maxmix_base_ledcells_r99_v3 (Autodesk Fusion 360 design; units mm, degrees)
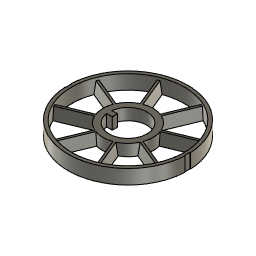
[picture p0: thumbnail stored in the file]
sketch "Sketch1" plane through (0, 0, 0) normal (0, 0, 1) x axis (1, 0, 0)
  circle C1 centre (0, 0) radius 21.7
  circle C2 centre (0, 0) radius 20.5
  circle C3 centre (0, 0) radius 9.125
  circle C4 centre (0, 0) radius 6.9
  point P1 (0, 0)
  point P2 (0, 0)
  coincident P1 P2
  concentric C1 C2
  concentric C2 C3
  concentric C2 C4
  dimension "d1" diameter C1 = 43.4
  dimension "d2" diameter C2 = 41
  dimension "d3" diameter C3 = 18.25
  dimension "d4" diameter C4 = 13.8
extrude "Extrude1" new body sketch "Sketch1" profile of C1 C2 along normal blind 5.2
extrude "Extrude2" new body sketch "Sketch1" profile of C3 C4 along normal blind 4.2
sketch "Sketch3" plane through (0, 0, 0) normal (0, 0, 1) x axis (1, 0, 0)
  line L1 (8.3042, 20.0482) -> (0, 0)
  line L2 (1.6888, 6.6901) -> (7.3715, 20.4096)
  line L3 (9.2193, 19.6442) -> (3.5365, 5.9248)
  line L4 (0, 20) -> (0, 2.5)
  circle C1 centre (0, 0) radius 21.7
  circle C2 centre (0, 0) radius 6.9
  point P4 (7.3715, 20.4096)
  point P7 (9.2193, 19.6442)
  point P3 (8.3042, 20.0482)
  point P5 (1.6888, 6.6901)
  point P6 (3.5365, 5.9248)
  point P1 (0, 0)
  point P2 (0, 0)
  parallel L1 L3
  symmetric L1 L2 L3
  coincident P4 C1
  coincident P7 C1
  coincident P3 C1
  coincident P5 C2
  coincident P6 C2
  coincident P1 P2
  dimension "d16" distance L2 L3 = 2
  dimension "d29" angle L1 L4 = 22.5
sketch "Sketch4" plane through (0, 0, 4.2) normal (0, 0, 1) x axis (-1, 0, 0)
  line L1 (-8.0746, -19.4939) -> (0, 0)
  line L2 (-2.736, -7.6505) -> (-7.7036, -19.6434)
  line L3 (-3.4751, -7.3443) -> (-8.4427, -19.3373)
  line L4 (0, -20) -> (0, -2.5)
  circle C1 centre (0, 0) radius 6.9
  circle C2 centre (0, 0) radius 21.7
  circle C3 centre (0, 0) radius 9.125
  circle C4 centre (0, 0) radius 20.5
  circle C5 centre (0, 0) radius 21.1
  circle C6 centre (0, 0) radius 8.125
  point P1 (0, 0)
  point P3 (0, 0)
  point P6 (-8.4427, -19.3373)
  point P4 (-7.7036, -19.6434)
  point P8 (-8.0746, -19.4939)
  point P13 (0, 0)
  point P7 (-3.4751, -7.3443)
  point P5 (-2.736, -7.6505)
  symmetric L1 L2 L3
  coincident P1 P3
  concentric C3 C5
  coincident P6 C5
  coincident P4 C5
  coincident P8 C5
  coincident P1 P13
  coincident P7 C6
  coincident P5 C6
  dimension "d17" distance L2 L3 = 0.8
  dimension "d20" distance C2 C5 = 0.6
  dimension "d21" distance C3 C6 = 1
  dimension "d30" angle L1 L4 = 22.5
loft "Loft3" sketch "Sketch3" + "Sketch4"
circular_pattern "C-Pattern2" TotalAngle 360
sketch "Sketch2" plane through (0, 0, 0) normal (0, 0, 1) x axis (1, 0, 0)
  line L1 (21.7, 0) -> (-21.7, 0)
  line L2 (0, -6.9) -> (0, 0)
  line L3 (21.5, 1) -> (21.6769, 1)
  line L4 (21.5, -1) -> (21.5, 1)
  line L5 (21.6769, -1) -> (21.5, -1)
  line L6 (-21.5, 1) -> (-21.6769, 1)
  line L7 (-21.5, -1) -> (-21.5, 1)
  line L8 (-21.6769, -1) -> (-21.5, -1)
  line L9 (-4.75, 0.95) -> (-6.8343, 0.95)
  line L10 (-4.75, -0.95) -> (-4.75, 0.95)
  line L11 (-6.8343, -0.95) -> (-4.75, -0.95)
  circle C1 centre (0, 0) radius 6.9
  circle C2 centre (0, 0) radius 21.7
  point P3 (0, 0)
  point P4 (0, 0)
  point P5 (0, -6.9)
  point P1 (0, 0)
  point P6 (21.6769, 1)
  point P9 (21.6769, -1)
  point P10 (-21.6769, 1)
  point P13 (-21.6769, -1)
  point P14 (-21.7, 0)
  point P15 (21.7, 0)
  point P16 (-6.8343, 0.95)
  point P19 (-6.8343, -0.95)
  point P17 (-4.75, 0.95)
  point P18 (-4.75, -0.95)
  horizontal L1
  coincident P3 P4
  coincident C1 P5
  vertical L2
  coincident P1 L1
  coincident C2 P6
  horizontal L3
  perpendicular L1 L4
  coincident C2 P9
  perpendicular L4 L5
  coincident C2 P10
  parallel L1 L6
  perpendicular L1 L7
  coincident C2 P13
  perpendicular L7 L8
  coincident C2 P14
  coincident C2 P15
  symmetric L1 L3 L5
  symmetric L1 L6 L8
  collinear L3 L6
  symmetric L2 L4 L7
  coincident C1 P16
  horizontal L9
  perpendicular L9 L10
  coincident C1 P19
  perpendicular L10 L11
  symmetric L1 L9 L11
  dimension "d9" distance L6 L8 = 2
  dimension "d10" distance P4 L7 = 21.5
  dimension "d27" distance P4 L10 = 4.75
  dimension "d28" distance P17 P18 = 1.9
extrude "Extrude5" cut sketch "Sketch2" profile of C2 L3 L4 L5 L6 L7 L8 no distance stored
extrude "Extrude6" add sketch "Sketch2" profile of C1 to an object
